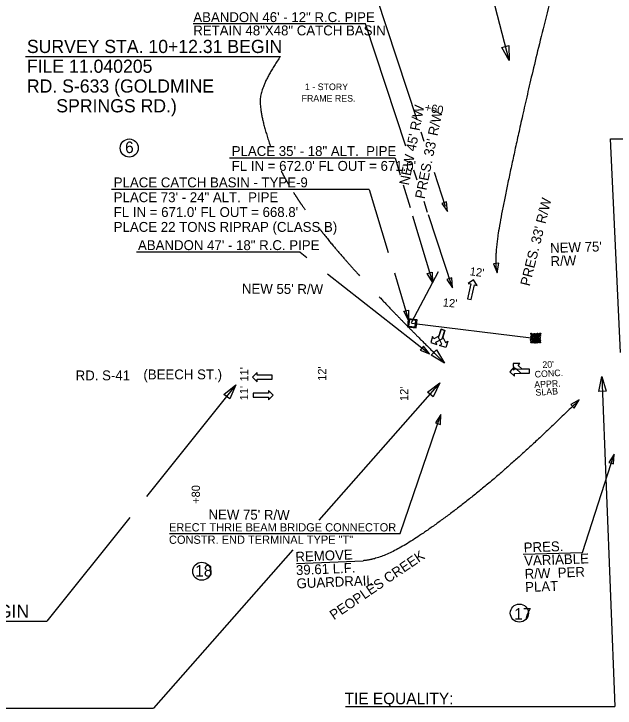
# Model space of a CAD drawing. Extents: x 16382402 to 16388022, y 46194326 to 46202918.
# Drawn here: x 16384585 to 16384949.7, y 46194799.5 to 46195220.7 of the extents above; entities that cross this region are included whole.
import ezdxf

# ---------------------------------------------------------------- set-up
doc = ezdxf.new("R2010")
doc.units = 0
for name, color, linetype in [('Default', 7, 'Continuous'), ('RD_EX_DV_Prop', 7, 'Continuous'), ('RD_EX_GuardRail', 7, 'Continuous'), ('RD_EX_RW', 7, 'Continuous'), ('RD_EX_RW_TX', 7, 'Continuous'), ('RD_HC_Data', 7, 'Continuous'), ('RD_PD_ALT2_TX', 7, 'Continuous'), ('RD_PD_Final_LnLine', 7, 'Continuous'), ('RD_PD_Final_TX', 7, 'Continuous'), ('RD_PD_RW_TX', 7, 'Continuous'), ('RD_TX_Bldg', 7, 'Continuous'), ('RD_TX_Drainage', 7, 'Continuous'), ('RD_TX_RoadID', 7, 'Continuous')]:
    doc.layers.add(name, color=color, linetype=linetype)

msp = doc.modelspace()

# ---------------------------------------------------------------- linework, layer by layer
at = {"layer": 'RD_EX_DV_Prop'}
for centre in [(16384654.97, 46195139.29), (16384698.96, 46194882.52), (16384891.58, 46194857.16)]:
    msp.add_circle(centre, 5.49, dxfattribs=at)
at = {"layer": 'RD_EX_GuardRail'}
for p, q in [((16384946.97, 46195144.93), (16384981.49, 46195144.93)), ((16384952.87, 46195015.28), (16384946.97, 46195144.93)), ((16384756.44, 46194887.22), (16384796.82, 46194888.93))]:
    msp.add_line(p, q, dxfattribs=at)
msp.add_open_spline([(16384927.96, 46194986.54), (16384894.55, 46194953.84), (16384849.46, 46194916.41), (16384809.49, 46194889.81), (16384796.82, 46194888.93)], degree=2, dxfattribs=at)
at = {"layer": 'RD_EX_RW'}
for p, q in [((16384929.86, 46194893.97), (16384949.06, 46194953.59)), ((16384893.94, 46194893), (16384929.86, 46194893.97))]:
    msp.add_line(p, q, dxfattribs=at)
msp.add_lwpolyline([(16384948.76, 46194947.6), (16384949.06, 46194953.59), (16384945.81, 46194948.55)], close=True, dxfattribs=at)
at = {"layer": 'RD_HC_Data'}
for p, q in [((16384941.63, 46195000.72), (16384949.45, 46194800.44)), ((16384843.28, 46194996.86), (16384770.04, 46194913.56)), ((16384754.18, 46194895.52), (16384669.76, 46194799.51)), ((16384427.9, 46194799.51), (16384669.76, 46194799.51)), ((16384786.07, 46194800.44), (16384949.45, 46194800.44))]:
    msp.add_line(p, q, dxfattribs=at)
at = {"layer": 'RD_PD_ALT2_TX'}
for p, q in [((16384819.36, 46194905.48), (16384844.03, 46194977.62)), ((16384679.44, 46194905.48), (16384819.36, 46194905.48))]:
    msp.add_line(p, q, dxfattribs=at)
msp.add_open_spline([(16384932.16, 46195312.48), (16384906.33, 46195215.29), (16384886.28, 46195127.34), (16384875.49, 46195071.8), (16384878.11, 46195063.52)], degree=2, dxfattribs=at)
at = {"layer": 'RD_PD_Final_LnLine'}
for points in [[(16384860.07, 46195047.85), (16384862.41, 46195047.33), (16384864.41, 46195056.28), (16384865.99, 46195055.93), (16384863.85, 46195059.3), (16384860.47, 46195057.16), (16384862.06, 46195056.8)], [(16384846.44, 46195028.64), (16384844.15, 46195029.36), (16384842.84, 46195025.18), (16384839.76, 46195023.58), (16384839, 46195025.02), (16384837.81, 46195021.21), (16384841.63, 46195020.02), (16384840.87, 46195021.46), (16384844.84, 46195023.54)], [(16384844.15, 46195029.36), (16384846.44, 46195028.64), (16384845.14, 46195024.47), (16384846.77, 46195021.4), (16384848.21, 46195022.16), (16384847.02, 46195018.34), (16384843.2, 46195019.53), (16384844.64, 46195020.28), (16384842.56, 46195024.25)], [(16384897.77, 46195002.78), (16384897.7, 46195005.18), (16384893.32, 46195005.04), (16384890.8, 46195007.44), (16384891.92, 46195008.62), (16384887.92, 46195008.5), (16384888.04, 46195004.5), (16384889.16, 46195005.69), (16384892.42, 46195002.62)], [(16384897.77, 46195002.78), (16384897.7, 46195005.18), (16384888.53, 46195004.9), (16384888.48, 46195006.53), (16384885.74, 46195003.61), (16384888.65, 46195000.87), (16384888.6, 46195002.5)], [(16384741.74, 46194999.09), (16384741.74, 46195001.49), (16384732.57, 46195001.49), (16384732.57, 46195003.12), (16384729.74, 46195000.29), (16384732.57, 46194997.46), (16384732.57, 46194999.09)], [(16384730.22, 46194990.6), (16384730.22, 46194988.2), (16384739.39, 46194988.2), (16384739.39, 46194986.57), (16384742.22, 46194989.4), (16384739.39, 46194992.23), (16384739.39, 46194990.6)]]:
    msp.add_lwpolyline(points, close=True, dxfattribs=at)
at = {"layer": 'RD_PD_Final_TX'}
for p, q in [((16384885.5, 46195192.3), (16384864.8, 46195272.09)), ((16384592.02, 46195194.9), (16384746.65, 46195194.9)), ((16384719.6, 46194995.65), (16384665.5, 46194927.95)), ((16384655.24, 46194915.12), (16384605.01, 46194852.28)), ((16384444.44, 46194852.28), (16384605.01, 46194852.28))]:
    msp.add_line(p, q, dxfattribs=at)
for points in [[(16384898.5, 46195026.72), (16384898.63, 46195026.9), (16384898.83, 46195026.91), (16384898.97, 46195026.77), (16384898.95, 46195026.56), (16384898.83, 46195026.46), (16384898.63, 46195026.47), (16384898.53, 46195026.57), (16384898.5, 46195026.72)], [(16384898.55, 46195024.99), (16384898.76, 46195025.29), (16384899.1, 46195025.31), (16384899.33, 46195025.06), (16384899.3, 46195024.73), (16384899.09, 46195024.55), (16384898.76, 46195024.58), (16384898.6, 46195024.73), (16384898.55, 46195024.99)], [(16384899.05, 46195026.49), (16384899.44, 46195026.65), (16384899.8, 46195026.62), (16384899.97, 46195026.45), (16384899.97, 46195026.16), (16384899.71, 46195025.83), (16384899.31, 46195025.63), (16384898.93, 46195025.62), (16384898.71, 46195025.77), (16384898.69, 46195026.07), (16384898.87, 46195026.34), (16384899.06, 46195026.5)], [(16384899.27, 46195024.38), (16384899.4, 46195024.56), (16384899.6, 46195024.57), (16384899.74, 46195024.42), (16384899.72, 46195024.22), (16384899.6, 46195024.12), (16384899.4, 46195024.13), (16384899.3, 46195024.22), (16384899.27, 46195024.38)], [(16384900.76, 46195024.78), (16384900.91, 46195024.38), (16384900.88, 46195024.02), (16384900.72, 46195023.85), (16384900.42, 46195023.86), (16384900.09, 46195024.12), (16384899.89, 46195024.52), (16384899.88, 46195024.9), (16384900.04, 46195025.11), (16384900.34, 46195025.13), (16384900.61, 46195024.96), (16384900.77, 46195024.76)], [(16384899.9, 46195025.74), (16384900.11, 46195026.04), (16384900.44, 46195026.06), (16384900.68, 46195025.81), (16384900.64, 46195025.48), (16384900.44, 46195025.3), (16384900.1, 46195025.33), (16384899.95, 46195025.48), (16384899.9, 46195025.74)], [(16384900.29, 46195026.53), (16384900.5, 46195026.83), (16384900.84, 46195026.85), (16384901.07, 46195026.61), (16384901.04, 46195026.27), (16384900.83, 46195026.09), (16384900.5, 46195026.12), (16384900.34, 46195026.27), (16384900.29, 46195026.53)], [(16384901.18, 46195026.17), (16384901.58, 46195026.33), (16384901.94, 46195026.3), (16384902.11, 46195026.13), (16384902.1, 46195025.84), (16384901.84, 46195025.51), (16384901.44, 46195025.31), (16384901.06, 46195025.3), (16384900.85, 46195025.45), (16384900.83, 46195025.75), (16384901, 46195026.02), (16384901.2, 46195026.18)], [(16384901.13, 46195024.48), (16384901.34, 46195024.78), (16384901.68, 46195024.8), (16384901.91, 46195024.56), (16384901.88, 46195024.22), (16384901.67, 46195024.05), (16384901.34, 46195024.07), (16384901.18, 46195024.22), (16384901.13, 46195024.48)], [(16384901.57, 46195026.65), (16384901.69, 46195026.83), (16384901.9, 46195026.84), (16384902.04, 46195026.7), (16384902.01, 46195026.49), (16384901.89, 46195026.39), (16384901.69, 46195026.41), (16384901.6, 46195026.5), (16384901.57, 46195026.65)], [(16384902.89, 46195024.83), (16384903.05, 46195024.44), (16384903.02, 46195024.07), (16384902.85, 46195023.9), (16384902.56, 46195023.91), (16384902.23, 46195024.17), (16384902.03, 46195024.57), (16384902.02, 46195024.95), (16384902.17, 46195025.16), (16384902.47, 46195025.18), (16384902.74, 46195025.01), (16384902.9, 46195024.81)], [(16384902.26, 46195026.57), (16384902.47, 46195026.87), (16384902.8, 46195026.89), (16384903.04, 46195026.65), (16384903, 46195026.31), (16384902.79, 46195026.14), (16384902.46, 46195026.16), (16384902.31, 46195026.31), (16384902.26, 46195026.57)], [(16384902.45, 46195025.68), (16384902.66, 46195025.98), (16384903, 46195026), (16384903.23, 46195025.76), (16384903.2, 46195025.42), (16384902.99, 46195025.25), (16384902.66, 46195025.27), (16384902.5, 46195025.42), (16384902.45, 46195025.68)], [(16384904.14, 46195024.64), (16384904.29, 46195024.24), (16384904.26, 46195023.88), (16384904.1, 46195023.71), (16384903.81, 46195023.72), (16384903.47, 46195023.98), (16384903.27, 46195024.38), (16384903.26, 46195024.76), (16384903.42, 46195024.97), (16384903.72, 46195024.99), (16384903.99, 46195024.82), (16384904.15, 46195024.62)], [(16384903.67, 46195026.81), (16384904.06, 46195026.97), (16384904.42, 46195026.94), (16384904.59, 46195026.78), (16384904.59, 46195026.48), (16384904.33, 46195026.15), (16384903.92, 46195025.95), (16384903.54, 46195025.94), (16384903.33, 46195026.09), (16384903.31, 46195026.4), (16384903.48, 46195026.67), (16384903.68, 46195026.82)], [(16384903.6, 46195025.5), (16384903.81, 46195025.8), (16384904.15, 46195025.81), (16384904.38, 46195025.57), (16384904.35, 46195025.23), (16384904.14, 46195025.06), (16384903.81, 46195025.09), (16384903.65, 46195025.24), (16384903.6, 46195025.5)], [(16384898.41, 46195021.52), (16384898.62, 46195021.81), (16384898.95, 46195021.83), (16384899.19, 46195021.59), (16384899.15, 46195021.25), (16384898.95, 46195021.08), (16384898.61, 46195021.1), (16384898.46, 46195021.26), (16384898.41, 46195021.52)], [(16384899.29, 46195022.95), (16384899.45, 46195022.55), (16384899.42, 46195022.19), (16384899.26, 46195022.02), (16384898.96, 46195022.03), (16384898.63, 46195022.29), (16384898.43, 46195022.69), (16384898.42, 46195023.07), (16384898.57, 46195023.28), (16384898.88, 46195023.3), (16384899.15, 46195023.13), (16384899.3, 46195022.93)], [(16384898.49, 46195023.95), (16384898.7, 46195024.25), (16384899.04, 46195024.27), (16384899.27, 46195024.03), (16384899.24, 46195023.69), (16384899.03, 46195023.52), (16384898.7, 46195023.54), (16384898.54, 46195023.69), (16384898.49, 46195023.95)], [(16384899.62, 46195021.98), (16384900.01, 46195022.13), (16384900.37, 46195022.1), (16384900.55, 46195021.94), (16384900.54, 46195021.64), (16384900.28, 46195021.31), (16384899.88, 46195021.11), (16384899.5, 46195021.1), (16384899.28, 46195021.26), (16384899.26, 46195021.56), (16384899.44, 46195021.83), (16384899.64, 46195021.99)], [(16384899.38, 46195023.65), (16384899.59, 46195023.95), (16384899.93, 46195023.97), (16384900.16, 46195023.73), (16384900.12, 46195023.39), (16384899.92, 46195023.22), (16384899.59, 46195023.24), (16384899.43, 46195023.39), (16384899.38, 46195023.65)], [(16384899.47, 46195022.67), (16384899.68, 46195022.97), (16384900.02, 46195022.99), (16384900.25, 46195022.75), (16384900.22, 46195022.41), (16384900.01, 46195022.24), (16384899.68, 46195022.26), (16384899.52, 46195022.41), (16384899.47, 46195022.67)], [(16384900.8, 46195023.48), (16384901.2, 46195023.63), (16384901.56, 46195023.6), (16384901.73, 46195023.44), (16384901.72, 46195023.15), (16384901.46, 46195022.81), (16384901.06, 46195022.61), (16384900.68, 46195022.61), (16384900.47, 46195022.76), (16384900.45, 46195023.06), (16384900.62, 46195023.33), (16384900.82, 46195023.49)], [(16384900.64, 46195021.4), (16384900.85, 46195021.7), (16384901.18, 46195021.72), (16384901.42, 46195021.48), (16384901.38, 46195021.14), (16384901.18, 46195020.97), (16384900.84, 46195020.99), (16384900.69, 46195021.14), (16384900.64, 46195021.4)], [(16384900.65, 46195022.06), (16384900.78, 46195022.24), (16384900.98, 46195022.25), (16384901.12, 46195022.11), (16384901.1, 46195021.9), (16384900.97, 46195021.8), (16384900.78, 46195021.81), (16384900.68, 46195021.91), (16384900.65, 46195022.06)], [(16384901.09, 46195022.43), (16384901.21, 46195022.61), (16384901.41, 46195022.62), (16384901.55, 46195022.47), (16384901.53, 46195022.27), (16384901.41, 46195022.16), (16384901.21, 46195022.18), (16384901.12, 46195022.27), (16384901.09, 46195022.43)], [(16384902.02, 46195022.78), (16384902.41, 46195022.93), (16384902.78, 46195022.9), (16384902.95, 46195022.74), (16384902.94, 46195022.45), (16384902.68, 46195022.11), (16384902.28, 46195021.91), (16384901.9, 46195021.9), (16384901.69, 46195022.06), (16384901.67, 46195022.36), (16384901.84, 46195022.63), (16384902.04, 46195022.79)], [(16384901.72, 46195021.42), (16384901.93, 46195021.72), (16384902.27, 46195021.73), (16384902.5, 46195021.49), (16384902.47, 46195021.15), (16384902.26, 46195020.98), (16384901.93, 46195021.01), (16384901.77, 46195021.16), (16384901.72, 46195021.42)], [(16384901.97, 46195023.51), (16384902.18, 46195023.81), (16384902.52, 46195023.82), (16384902.75, 46195023.58), (16384902.72, 46195023.24), (16384902.51, 46195023.07), (16384902.18, 46195023.1), (16384902.03, 46195023.25), (16384901.97, 46195023.51)], [(16384902.54, 46195021.64), (16384902.75, 46195021.93), (16384903.08, 46195021.95), (16384903.32, 46195021.71), (16384903.28, 46195021.37), (16384903.07, 46195021.2), (16384902.74, 46195021.23), (16384902.59, 46195021.38), (16384902.54, 46195021.64)], [(16384902.84, 46195023.49), (16384903.05, 46195023.79), (16384903.38, 46195023.81), (16384903.62, 46195023.57), (16384903.58, 46195023.23), (16384903.38, 46195023.06), (16384903.05, 46195023.08), (16384902.89, 46195023.23), (16384902.84, 46195023.49)], [(16384903.14, 46195022.77), (16384903.27, 46195022.95), (16384903.47, 46195022.96), (16384903.61, 46195022.82), (16384903.59, 46195022.61), (16384903.47, 46195022.51), (16384903.27, 46195022.52), (16384903.17, 46195022.61), (16384903.14, 46195022.77)], [(16384904.29, 46195021.96), (16384904.45, 46195021.56), (16384904.41, 46195021.2), (16384904.25, 46195021.03), (16384903.96, 46195021.04), (16384903.62, 46195021.3), (16384903.42, 46195021.7), (16384903.42, 46195022.08), (16384903.57, 46195022.29), (16384903.87, 46195022.31), (16384904.14, 46195022.14), (16384904.3, 46195021.94)], [(16384903.79, 46195023.4), (16384903.92, 46195023.58), (16384904.12, 46195023.59), (16384904.26, 46195023.45), (16384904.24, 46195023.24), (16384904.12, 46195023.14), (16384903.92, 46195023.15), (16384903.82, 46195023.25), (16384903.79, 46195023.4)], [(16384903.97, 46195022.62), (16384904.1, 46195022.8), (16384904.3, 46195022.81), (16384904.44, 46195022.67), (16384904.42, 46195022.47), (16384904.29, 46195022.36), (16384904.1, 46195022.38), (16384904, 46195022.47), (16384903.97, 46195022.62)]]:
    msp.add_lwpolyline(points, dxfattribs=at)
for points in [[(16384746.65, 46195194.9), (16384735.15, 46195178.13), (16384733.77, 46195160.32), (16384740.49, 46195140.64)], [(16384747.17, 46195125.21), (16384748.59, 46195122.46), (16384750.15, 46195119.68), (16384751.83, 46195116.85)], [(16384754.57, 46195112.4), (16384756.77, 46195108.94), (16384759.15, 46195105.42), (16384761.71, 46195101.84)], [(16384770, 46195090.79), (16384777.24, 46195081.56), (16384785.51, 46195071.92), (16384794.7, 46195061.84)], [(16384806.56, 46195049.07), (16384818.58, 46195036.39), (16384831.85, 46195023.01), (16384846.14, 46195008.83)]]:
    msp.add_open_spline(points, degree=2, dxfattribs=at)
at = {"layer": 'RD_TX_Drainage'}
for p, q in [((16384829.51, 46195156.34), (16384798.86, 46195249.48)), ((16384798.34, 46195214.58), (16384693.77, 46195214.58)), ((16384822.73, 46195140.47), (16384798.34, 46195214.58)), ((16384833.82, 46195143.27), (16384831.97, 46195148.87)), ((16384816.33, 46195133.08), (16384715.84, 46195133.08)), ((16384816.33, 46195133.08), (16384819.37, 46195122.99)), ((16384829.56, 46195119.7), (16384827.52, 46195125.92)), ((16384846.82, 46195103.75), (16384840.03, 46195124.4)), ((16384800.56, 46195114.07), (16384644.28, 46195114.07)), ((16384800.56, 46195114.07), (16384812.03, 46195075.98)), ((16384821.19, 46195116.93), (16384825.34, 46195103.15)), ((16384835.97, 46195100.25), (16384833.77, 46195106.93)), ((16384826.83, 46195098.21), (16384838.99, 46195057.81)), ((16384851.03, 46195054.49), (16384836.43, 46195098.84)), ((16384758.55, 46195076.15), (16384659.43, 46195076.15)), ((16384758.55, 46195076.15), (16384762.67, 46195072.9)), ((16384775.26, 46195063), (16384837.03, 46195014.41)), ((16384815.77, 46195063.58), (16384824.42, 46195034.83)), ((16384842.34, 46195064.16), (16384826.02, 46195033.2)), ((16384824.64, 46195033.19), (16384824.64, 46195033.19)), ((16384826.22, 46195033), (16384898.67, 46195024.04)), ((16384826.86, 46195034.94), (16384826.86, 46195034.94)), ((16384826.86, 46195034.94), (16384826.86, 46195034.94)), ((16384826.92, 46195035.44), (16384826.92, 46195035.44)), ((16384826.39, 46195030.97), (16384826.39, 46195030.97)), ((16384826.39, 46195030.97), (16384826.39, 46195030.97)), ((16384828.61, 46195032.72), (16384828.61, 46195032.72))]:
    msp.add_line(p, q, dxfattribs=at)
for points in [[(16384885.2, 46195201.57), (16384885.5, 46195192.3), (16384880.87, 46195200.34)], [(16384844.58, 46195105.64), (16384848.05, 46195100.75), (16384847.49, 46195106.73)], [(16384875.96, 46195069.12), (16384878.11, 46195063.52), (16384879.05, 46195069.44)], [(16384838.6, 46195063.98), (16384838.99, 46195057.81), (16384835.74, 46195063.07)], [(16384847.66, 46195059.45), (16384851.03, 46195054.49), (16384850.59, 46195060.47)], [(16384824.32, 46195041.01), (16384824.42, 46195034.83), (16384821.42, 46195040.23)], [(16384824.24, 46195035.76), (16384823.65, 46195030.79), (16384829.01, 46195030.16), (16384829.6, 46195035.12)], [(16384828.85, 46195034.71), (16384824.87, 46195035.18), (16384824.4, 46195031.2), (16384828.38, 46195030.74)], [(16384831.49, 46195016.72), (16384837.03, 46195014.41), (16384833.39, 46195019.18)], [(16384841.37, 46195016.79), (16384846.14, 46195008.83), (16384838.19, 46195013.6)], [(16384939.73, 46194991.64), (16384941.63, 46195000.72), (16384944.23, 46194991.82)], [(16384712.41, 46194989.79), (16384719.6, 46194995.65), (16384716.02, 46194987.09)], [(16384835.88, 46194991.27), (16384843.28, 46194996.86), (16384839.38, 46194988.44)], [(16384924.89, 46194981.39), (16384927.96, 46194986.54), (16384922.73, 46194983.61)], [(16384843.75, 46194971.63), (16384844.03, 46194977.62), (16384840.79, 46194972.57)]]:
    msp.add_lwpolyline(points, close=True, dxfattribs=at)

# ---------------------------------------------------------------- texts
at = {"layer": 'Default'}
for s, rotation, p in [("20'", 3.2141, (16384905.65, 46195005.79)), ('CONC.', 3.6881, (16384901, 46194999.98)), ('APPR.', 2.7523, (16384900.7, 46194993.77)), ('SLAB', 3.6651, (16384901.5, 46194989))]:
    msp.add_text(s, height=4, rotation=rotation, dxfattribs=at).set_placement(p)
at = {"layer": 'RD_EX_DV_Prop'}
for s, p in [('6', (16384652.45, 46195136.21)), ('18', (16384694.97, 46194879.34)), ('17', (16384888.49, 46194853.21))]:
    msp.add_text(s, height=7, dxfattribs=at).set_placement(p)
at = {"layer": 'RD_EX_GuardRail'}
for s, p in [('REMOVE ', (16384755.87, 46194888.26)), ('39.61 L.F.', (16384756.21, 46194880.19)), ('GUARDRAIL', (16384756.56, 46194872.12))]:
    msp.add_text(s, height=6, rotation=2.436, dxfattribs=at).set_placement(p)
at = {"layer": 'RD_EX_RW_TX'}
for s, rotation, p in [("PRES. 33' R/W ", 78.4537, (16384834.09, 46195108.08)), ("PRES. 33' R/W ", 75.9223, (16384897.85, 46195055.16)), ('PRES. ', 2.0851, (16384894.33, 46194893.92)), ('VARIABLE ', 2.0851, (16384894.62, 46194885.92)), ('R/W  PER ', 2.0851, (16384894.92, 46194877.93)), ('PLAT', 2.0851, (16384895.21, 46194869.93))]:
    msp.add_text(s, height=6, rotation=rotation, dxfattribs=at).set_placement(p)
at = {"layer": 'RD_HC_Data'}
msp.add_text('TIE EQUALITY:', height=7, dxfattribs=at).set_placement((16384785.56, 46194801.86))
at = {"layer": 'RD_PD_ALT2_TX'}
for s, p in [('ERECT THRIE BEAM BRIDGE CONNECTOR', (16384679.07, 46194906.68)), ('CONSTR. END TERMINAL TYPE "T"', (16384679.07, 46194899.18))]:
    msp.add_text(s, height=5, dxfattribs=at).set_placement(p)
at = {"layer": 'RD_PD_Final_TX'}
for s, p in [('SURVEY STA. 10+12.31 BEGIN', (16384592.88, 46195196.91)), ('FILE 11.040205', (16384592.88, 46195184.91)), ('RD. S-633 (GOLDMINE ', (16384592.88, 46195172.91)), ('      SPRINGS RD.)', (16384592.88, 46195160.91)), ('SURVEY STA. 12+00.0 BEGIN', (16384445.3, 46194854.3))]:
    msp.add_text(s, height=8, dxfattribs=at).set_placement(p)
for s, rotation, p in [("12'", 352.3729, (16384861.28, 46195062.14)), ("12'", 354.8471, (16384844.99, 46195043.2)), ("11'", 90, (16384727.23, 46194997.63)), ("12'", 90, (16384774.41, 46194998.09)), ("11'", 90, (16384727.09, 46194986.24)), ("12'", 90, (16384824.19, 46194985.83))]:
    msp.add_text(s, height=5, rotation=rotation, dxfattribs=at).set_placement(p)
at = {"layer": 'RD_PD_RW_TX'}
for s, height, rotation, p in [("NEW 45' R/W", 6, 78.9376, (16384824.54, 46195116.38)), ('+60', 5, 350.1753, (16384833.87, 46195161.62)), ("NEW 75' ", 6, 1.7539, (16384910.33, 46195075.63)), ('R/W', 6, 1.7539, (16384910.58, 46195067.64)), ("NEW 55' R/W", 6, 359.6025, (16384723.29, 46195050.98)), ('+80', 5, 90, (16384697.83, 46194923.43)), ("NEW 75' R/W", 6, 359.5951, (16384702.99, 46194914.01))]:
    msp.add_text(s, height=height, rotation=rotation, dxfattribs=at).set_placement(p)
at = {"layer": 'RD_TX_Bldg'}
for s, p in [('1 - STORY', (16384761.54, 46195174.42)), ('FRAME RES.', (16384759.49, 46195167.42))]:
    msp.add_text(s, height=4, dxfattribs=at).set_placement(p)
at = {"layer": 'RD_TX_Drainage'}
for s, p in [('ABANDON 46\' - 12" R.C. PIPE', (16384693.81, 46195215.69)), ('RETAIN 48"X48" CATCH BASIN', (16384693.81, 46195207.61)), ('PLACE 35\' - 18" ALT.  PIPE', (16384717.12, 46195134.44)), ("FL IN = 672.0' FL OUT = 671.0'", (16384717.12, 46195125.44)), ('PLACE CATCH BASIN - TYPE-9', (16384645.56, 46195115.43)), ('PLACE 73\' - 24" ALT.  PIPE', (16384645.56, 46195106.43)), ("FL IN = 671.0' FL OUT = 668.8'", (16384645.56, 46195097.43)), ('PLACE 22 TONS RIPRAP (CLASS B)', (16384645.56, 46195088.43)), ('ABANDON 47\' - 18" R.C. PIPE', (16384660.26, 46195077.36))]:
    msp.add_text(s, height=6, dxfattribs=at).set_placement(p)
at = {"layer": 'RD_TX_RoadID'}
for s, p in [('RD. S-41', (16384622.45, 46194998.35)), ('(BEECH ST.)', (16384663.55, 46194998.95))]:
    msp.add_text(s, height=6, dxfattribs=at).set_placement(p)
msp.add_text('PEOPLES CREEK', height=6, rotation=34.1654, dxfattribs=at).set_placement((16384779.11, 46194852.78))

doc.saveas('drawing.dxf')
